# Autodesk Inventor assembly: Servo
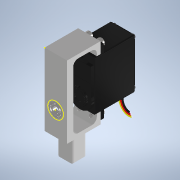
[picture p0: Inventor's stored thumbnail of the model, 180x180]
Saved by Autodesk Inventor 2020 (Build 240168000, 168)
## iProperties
Created: 2023-10
Part Number: Servo
Document SubType Name: Assembly
Designer: bruno
Author: bruno
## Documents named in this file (5)
- C:\Users\bruno\Documents\1-Cours-2023-24\Maquettes-Inventor\Pince-robot-Dobot\HS422\Servo.iam
- C:\Users\bruno\Documents\1-Cours-2023-24\Maquettes-Inventor\Pince-robot-Dobot\HS422\corps_HS422.ipt
- C:\Users\bruno\Documents\1-Cours-2023-24\Maquettes-Inventor\Pince-robot-Dobot\support-servo.ipt
- C:\Users\bruno\Documents\1-Cours-2023-24\Maquettes-Inventor\Pince-robot-Dobot\HS422\Servo\Design Accelerator\Roulement1.iam
- C:\Users\bruno\Documents\Inventor\Content Center Files\R2020\fr-FR\KS B 1003\KS B 1003 - M 3 x 6.ipt
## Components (7 placed, 4 different names)
1. corps_HS422:1 — Placage:1, Placage:2, Affleurement:1, Logement:1, Logement:2, Logement:3, Logement:4
2. support-servo:1 — Placage:1, Placage:2, Affleurement:1, Placage:3, Affleurement:2
3. Roulement:1 [sub-assembly] — Placage:3, Affleurement:2
4. KS B 1003 - Métrique M 3 x 6:1 — Logement:2
5. KS B 1003 - Métrique M 3 x 6:2 — Logement:4
6. KS B 1003 - Métrique M 3 x 6:3 — Logement:3
7. KS B 1003 - Métrique M 3 x 6:4 — Logement:1
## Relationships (9: Insert 4, Mate 3, Flush 2)
- Placage:1 [Mate]: corps_HS422:1 ↔ support-servo:1
- Placage:2 [Mate]: corps_HS422:1 ↔ support-servo:1
- Affleurement:1 [Flush]: corps_HS422:1 ↔ support-servo:1
- Placage:3 [Mate]: support-servo:1 ↔ Roulement:1
- Affleurement:2 [Flush]: support-servo:1 ↔ Roulement:1
- Logement:1 [Insert]: corps_HS422:1 ↔ KS B 1003 - Métrique M 3 x 6:4
- Logement:2 [Insert]: corps_HS422:1 ↔ KS B 1003 - Métrique M 3 x 6:1
- Logement:3 [Insert]: corps_HS422:1 ↔ KS B 1003 - Métrique M 3 x 6:3
- Logement:4 [Insert]: corps_HS422:1 ↔ KS B 1003 - Métrique M 3 x 6:2
